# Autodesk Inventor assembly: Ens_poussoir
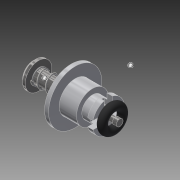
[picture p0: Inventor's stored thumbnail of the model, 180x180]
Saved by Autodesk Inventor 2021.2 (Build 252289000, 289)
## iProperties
Created: 2018-06
Part Number: Ens_poussoir
Material: Générique
Document SubType Name: Assembly
Designer: Fabian Perrée
Mass: 5.90054 g
Surface Area: 24.3283 cm^2
Volume: 1.88874 cm^3
Density: 3.12406 g/cm^3
Author: Fabian Perrée
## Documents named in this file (5)
- C:\Users\Fabian\Google Drive\04_CAO-DAO\01_Exercices\01_Inventor\01_Fichiers_exercice_Inventor\01_Definitif\Capteur\Ens_poussoir\Ens_poussoir.iam
- C:\Users\Fabian\Google Drive\04_CAO-DAO\01_Exercices\01_Inventor\01_Fichiers_exercice_Inventor\01_Definitif\Capteur\Ens_poussoir\Composants\Guide.ipt
- C:\Users\Fabian\Google Drive\04_CAO-DAO\01_Exercices\01_Inventor\01_Fichiers_exercice_Inventor\01_Definitif\Capteur\Ens_poussoir\Composants\Poussoir.ipt
- C:\Users\Fabian\Google Drive\04_CAO-DAO\01_Exercices\01_Inventor\01_Fichiers_exercice_Inventor\01_Definitif\Capteur\Ens_poussoir\Composants\Joint.ipt
- C:\Users\Fabian\Google Drive\04_CAO-DAO\01_Exercices\01_Inventor\01_Fichiers_exercice_Inventor\01_Definitif\Capteur\Capteur\Design Accelerator\Ressort de compression12.ipt
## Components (4 placed, 4 different names)
1. Guide:1 — Tangente:2, Placage:2
2. Poussoir:1 — Placage:1, Placage:2, Placage:3, Placage:4
3. Joint:1 — Tangente:2, Placage:1
4. Ressort de compression1:1 — Placage:3, Placage:4
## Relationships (5: Mate 4, Tangent 1)
- Tangente:2: Guide:1 ↔ Joint:1
- Placage:1 [Mate]: Poussoir:1 ↔ Joint:1
- Placage:2 [Mate]: Guide:1 ↔ Poussoir:1
- Placage:3 [Mate]: Poussoir:1 ↔ Ressort de compression1:1
- Placage:4 [Mate]: Poussoir:1 ↔ Ressort de compression1:1
